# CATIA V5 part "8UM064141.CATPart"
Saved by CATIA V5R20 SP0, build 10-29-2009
Part number: 8UM064141
Revision: ANY
Definition: UNKNOWN
Nomenclature: 8UM064141
Source: Unknown
Bounding box of the stored display mesh (mm): x -41 to 0, y 0 to 41, z 0 to 3.8
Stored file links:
  C:\Users\Utente\Desktop\IO LAVORO\3D X SITO CF\X SITO\3D files UM\UM064242 PRODUCT\8UM064141.CATPart
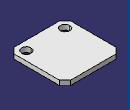
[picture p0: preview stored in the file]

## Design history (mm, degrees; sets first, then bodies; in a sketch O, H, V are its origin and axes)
Body1 "Chaflán3" (main body)
  Solid1: solid without history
